(* Logix 5000 project; controller DNP3Master vendor 1 type 14 code 96 rev 19.13; software revision 19.01; part 5 of 5 *)

ADD_ON_INSTRUCTION PSDNP3EventG40V02   (* revision 1.0, vendor ProSoft Technology Inc *)
// Processes DNP3 Event and updates corresponding static DNP3 object. (Report by Exception.)
// G40V02 - Analog Output Status - 16bit with Status
VAR_IN_OUT
   EventBuffer : PSDNP3MasterEvent[1]; {required}
END_VAR
VAR_INPUT
   BufferSize : DINT; {required}
   CurrentBufferIndex : DINT; {required}
   Reset : BOOL; {required}
   OutstationNodeAddress : INT; {required}
   OutstationIPAddress0 : INT; {required}
   OutstationIPAddress1 : INT; {required}
   OutstationIPAddress2 : INT; {required}
   OutstationIPAddress3 : INT; {required}
END_VAR
VAR_IN_OUT
   DNP3StaticObject : PSDNP3AnalogOutputStatus16Flag[1]; {required}
END_VAR
VAR_INPUT
   MaxtElementCount : DINT; {required}
END_VAR
VAR_OUTPUT
   EventsProcessed : DINT; {access Read Only, visible}
   LastElementIndex : DINT; {access Read Only, visible}
   LastValue : DINT; {access Read Only, visible}
   LastStatus : SINT; {access Read Only, visible}
   CurrentUnloadIndex : DINT; {access Read Only, visible}
END_VAR
VAR
   UnloadIndex : DINT; {access None}
   EnableInTemp : BOOL; {access None}
   InitialScan : BOOL; {access None}
   EntryValidForProcessing : BOOL; {access None}
   ElementIndex : DINT; {access None}
   NextIndex : DINT; {access None}
   ResetPulse : BOOL; {access None}
   ResetONS : BOOL; {access None}
END_VAR

ROUTINE Logic   (* ladder *)
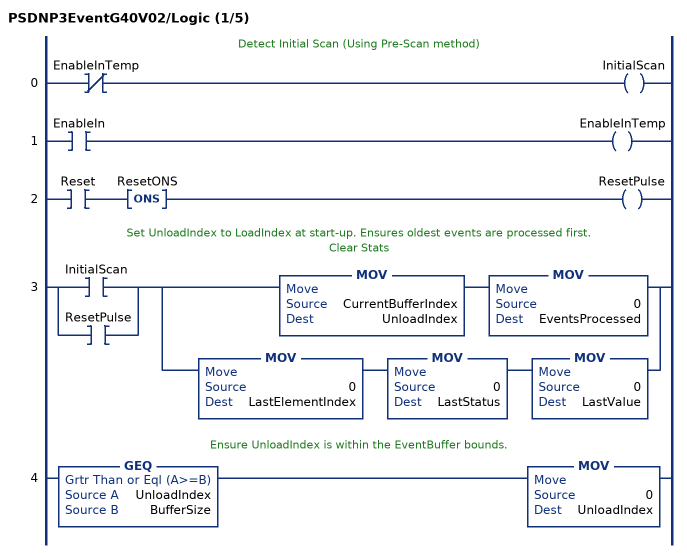
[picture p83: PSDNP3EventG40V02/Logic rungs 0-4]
   // Detect Initial Scan (Using Pre-Scan method)
   0: XIO(EnableInTemp)OTE(InitialScan);
   1: XIC(EnableIn)OTE(EnableInTemp);
   2: XIC(Reset)ONS(ResetONS)OTE(ResetPulse);
   // Set UnloadIndex to LoadIndex at start-up. Ensures oldest events are processed first.
   // Clear Stats
   3: [XIC(InitialScan) ,XIC(ResetPulse) ][MOV(CurrentBufferIndex,UnloadIndex) MOV(0,EventsProcessed) ,MOV(0,LastElementIndex) MOV(0,LastStatus) MOV(0,LastValue) ];
   // Ensure UnloadIndex is within the EventBuffer bounds.
   4: GEQ(UnloadIndex,BufferSize)MOV(0,UnloadIndex);
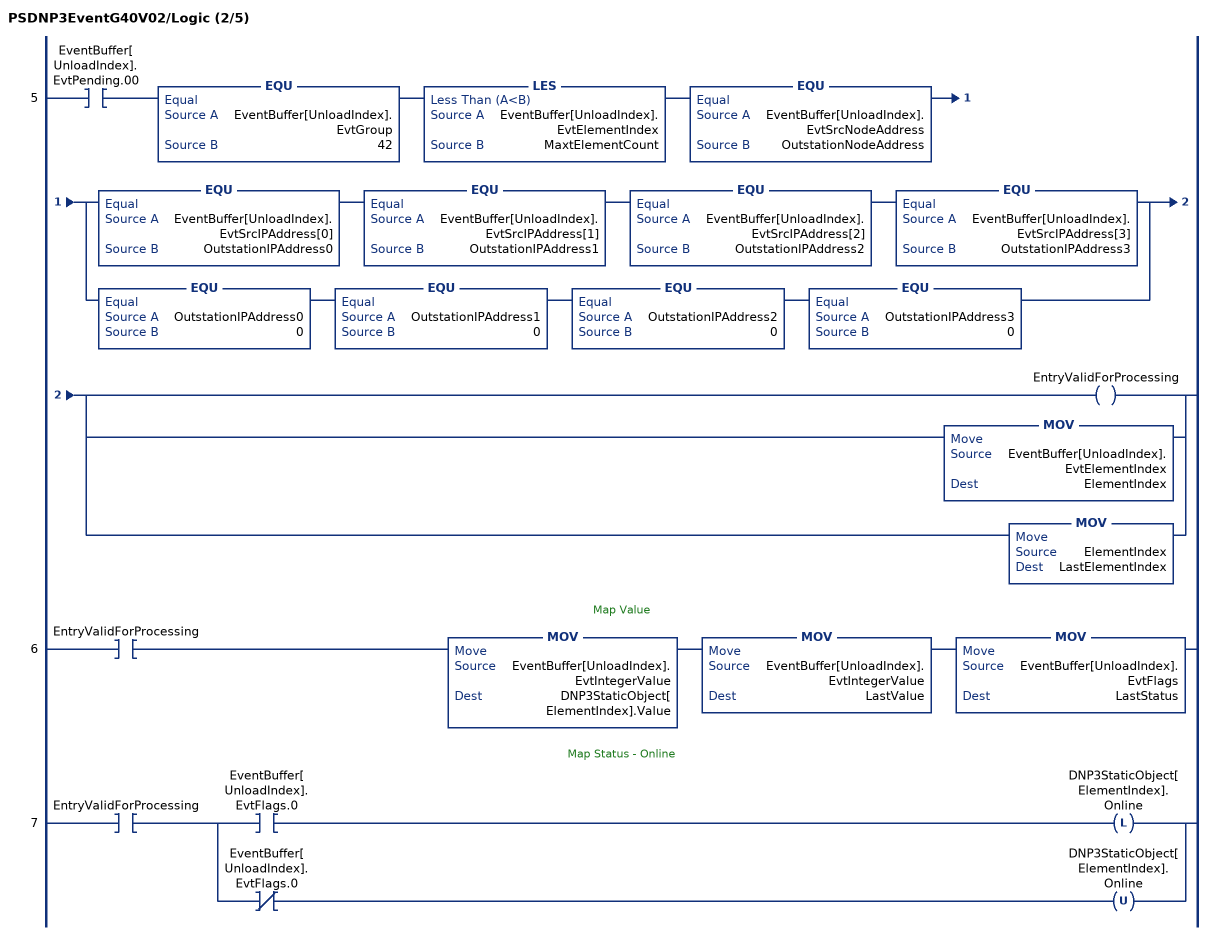
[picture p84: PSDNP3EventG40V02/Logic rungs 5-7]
   5: XIC(EventBuffer[UnloadIndex].EvtPending.00)EQU(EventBuffer[UnloadIndex].EvtGroup,42)LES(EventBuffer[UnloadIndex].EvtElementIndex,MaxtElementCount)EQU(EventBuffer[UnloadIndex].EvtSrcNodeAddress,OutstationNodeAddress)[EQU(EventBuffer[UnloadIndex].EvtSrcIPAddress[0],OutstationIPAddress0) EQU(EventBuffer[UnloadIndex].EvtSrcIPAddress[1],OutstationIPAddress1) EQU(EventBuffer[UnloadIndex].EvtSrcIPAddress[2],OutstationIPAddress2) EQU(EventBuffer[UnloadIndex].EvtSrcIPAddress[3],OutstationIPAddress3) ,EQU(OutstationIPAddress0,0) EQU(OutstationIPAddress1,0) EQU(OutstationIPAddress2,0) EQU(OutstationIPAddress3,0) ][OTE(EntryValidForProcessing) ,MOV(EventBuffer[UnloadIndex].EvtElementIndex,ElementIndex) ,MOV(ElementIndex,LastElementIndex) ];
   // Map Value
   6: XIC(EntryValidForProcessing)MOV(EventBuffer[UnloadIndex].EvtIntegerValue,DNP3StaticObject[ElementIndex].Value)MOV(EventBuffer[UnloadIndex].EvtIntegerValue,LastValue)MOV(EventBuffer[UnloadIndex].EvtFlags,LastStatus);
   // Map Status - Online
   7: XIC(EntryValidForProcessing)[XIC(EventBuffer[UnloadIndex].EvtFlags.0) OTL(DNP3StaticObject[ElementIndex].Online) ,XIO(EventBuffer[UnloadIndex].EvtFlags.0) OTU(DNP3StaticObject[ElementIndex].Online) ];
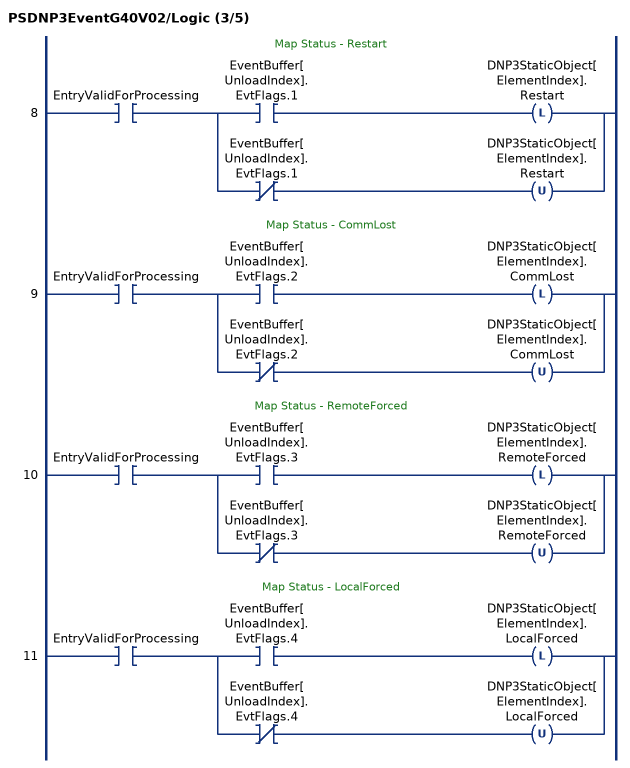
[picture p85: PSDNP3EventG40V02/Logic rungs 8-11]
   // Map Status - Restart
   8: XIC(EntryValidForProcessing)[XIC(EventBuffer[UnloadIndex].EvtFlags.1) OTL(DNP3StaticObject[ElementIndex].Restart) ,XIO(EventBuffer[UnloadIndex].EvtFlags.1) OTU(DNP3StaticObject[ElementIndex].Restart) ];
   // Map Status - CommLost
   9: XIC(EntryValidForProcessing)[XIC(EventBuffer[UnloadIndex].EvtFlags.2) OTL(DNP3StaticObject[ElementIndex].CommLost) ,XIO(EventBuffer[UnloadIndex].EvtFlags.2) OTU(DNP3StaticObject[ElementIndex].CommLost) ];
   // Map Status - RemoteForced
   10: XIC(EntryValidForProcessing)[XIC(EventBuffer[UnloadIndex].EvtFlags.3) OTL(DNP3StaticObject[ElementIndex].RemoteForced) ,XIO(EventBuffer[UnloadIndex].EvtFlags.3) OTU(DNP3StaticObject[ElementIndex].RemoteForced) ];
   // Map Status - LocalForced
   11: XIC(EntryValidForProcessing)[XIC(EventBuffer[UnloadIndex].EvtFlags.4) OTL(DNP3StaticObject[ElementIndex].LocalForced) ,XIO(EventBuffer[UnloadIndex].EvtFlags.4) OTU(DNP3StaticObject[ElementIndex].LocalForced) ];
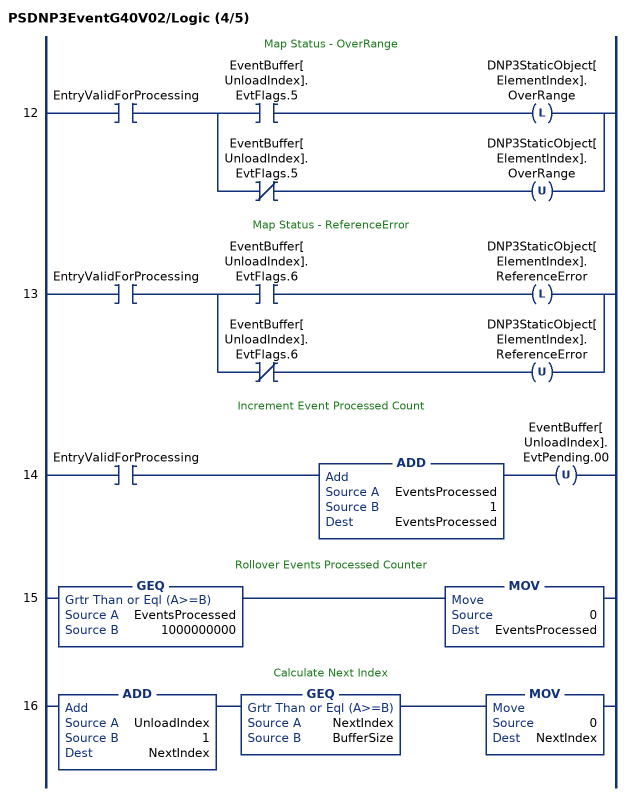
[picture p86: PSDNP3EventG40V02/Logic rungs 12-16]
   // Map Status - OverRange
   12: XIC(EntryValidForProcessing)[XIC(EventBuffer[UnloadIndex].EvtFlags.5) OTL(DNP3StaticObject[ElementIndex].OverRange) ,XIO(EventBuffer[UnloadIndex].EvtFlags.5) OTU(DNP3StaticObject[ElementIndex].OverRange) ];
   // Map Status - ReferenceError
   13: XIC(EntryValidForProcessing)[XIC(EventBuffer[UnloadIndex].EvtFlags.6) OTL(DNP3StaticObject[ElementIndex].ReferenceError) ,XIO(EventBuffer[UnloadIndex].EvtFlags.6) OTU(DNP3StaticObject[ElementIndex].ReferenceError) ];
   // Increment Event Processed Count
   14: XIC(EntryValidForProcessing)ADD(EventsProcessed,1,EventsProcessed)OTU(EventBuffer[UnloadIndex].EvtPending.00);
   // Rollover Events Processed Counter
   15: GEQ(EventsProcessed,1000000000)MOV(0,EventsProcessed);
   // Calculate Next Index
   16: ADD(UnloadIndex,1,NextIndex)GEQ(NextIndex,BufferSize)MOV(0,NextIndex);
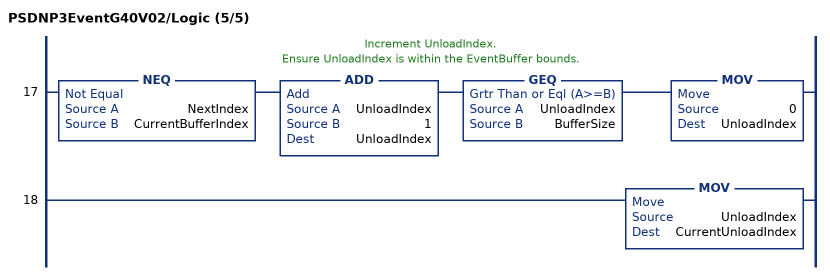
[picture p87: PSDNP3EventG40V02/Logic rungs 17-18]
   // Increment UnloadIndex.
   // Ensure UnloadIndex is within the EventBuffer bounds.
   17: NEQ(NextIndex,CurrentBufferIndex)ADD(UnloadIndex,1,UnloadIndex)GEQ(UnloadIndex,BufferSize)MOV(0,UnloadIndex);
   18: MOV(UnloadIndex,CurrentUnloadIndex);
END_ROUTINE
END_ADD_ON_INSTRUCTION

ADD_ON_INSTRUCTION PSDNP3EventG40V03   (* revision 1.0, vendor ProSoft Technology Inc *)
// Processes DNP3 Event and updates corresponding static DNP3 object. (Report by Exception.)
// G40V03 - Analog Output Status - Real with Status
VAR_IN_OUT
   EventBuffer : PSDNP3MasterEvent[1]; {required}
END_VAR
VAR_INPUT
   BufferSize : DINT; {required}
   CurrentBufferIndex : DINT; {required}
   Reset : BOOL; {required}
   OutstationNodeAddress : INT; {required}
   OutstationIPAddress0 : INT; {required}
   OutstationIPAddress1 : INT; {required}
   OutstationIPAddress2 : INT; {required}
   OutstationIPAddress3 : INT; {required}
END_VAR
VAR_IN_OUT
   DNP3StaticObject : PSDNP3AnalogOutputStatusRealFlag[1]; {required}
END_VAR
VAR_INPUT
   MaxtElementCount : DINT; {required}
END_VAR
VAR_OUTPUT
   EventsProcessed : DINT; {access Read Only, visible}
   LastElementIndex : DINT; {access Read Only, visible}
   LastValue : REAL; {access Read Only, visible}
   LastStatus : SINT; {access Read Only, visible}
   CurrentUnloadIndex : DINT; {access Read Only, visible}
END_VAR
VAR
   UnloadIndex : DINT; {access None}
   EnableInTemp : BOOL; {access None}
   InitialScan : BOOL; {access None}
   EntryValidForProcessing : BOOL; {access None}
   ElementIndex : DINT; {access None}
   NextIndex : DINT; {access None}
   ResetPulse : BOOL; {access None}
   ResetONS : BOOL; {access None}
END_VAR

ROUTINE Logic   (* ladder *)
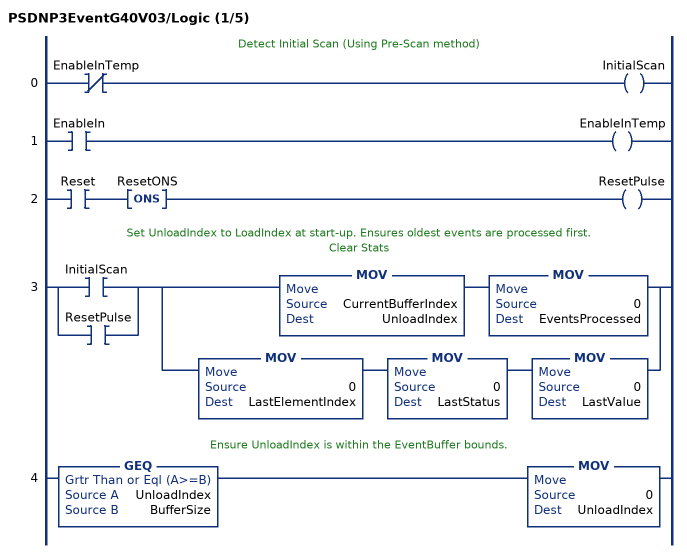
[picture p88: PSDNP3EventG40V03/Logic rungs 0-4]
   // Detect Initial Scan (Using Pre-Scan method)
   0: XIO(EnableInTemp)OTE(InitialScan);
   1: XIC(EnableIn)OTE(EnableInTemp);
   2: XIC(Reset)ONS(ResetONS)OTE(ResetPulse);
   // Set UnloadIndex to LoadIndex at start-up. Ensures oldest events are processed first.
   // Clear Stats
   3: [XIC(InitialScan) ,XIC(ResetPulse) ][MOV(CurrentBufferIndex,UnloadIndex) MOV(0,EventsProcessed) ,MOV(0,LastElementIndex) MOV(0,LastStatus) MOV(0,LastValue) ];
   // Ensure UnloadIndex is within the EventBuffer bounds.
   4: GEQ(UnloadIndex,BufferSize)MOV(0,UnloadIndex);
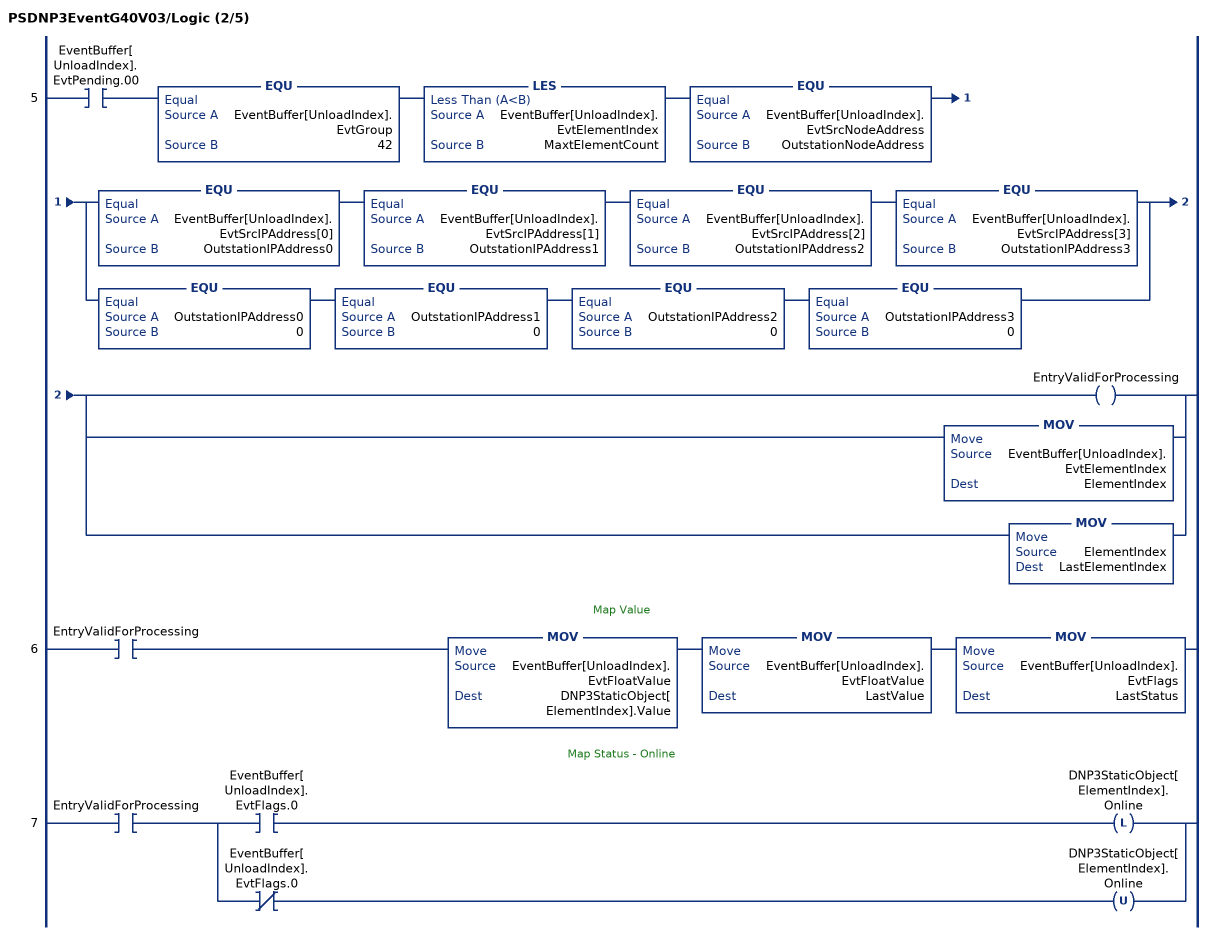
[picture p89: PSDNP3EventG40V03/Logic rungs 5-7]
   5: XIC(EventBuffer[UnloadIndex].EvtPending.00)EQU(EventBuffer[UnloadIndex].EvtGroup,42)LES(EventBuffer[UnloadIndex].EvtElementIndex,MaxtElementCount)EQU(EventBuffer[UnloadIndex].EvtSrcNodeAddress,OutstationNodeAddress)[EQU(EventBuffer[UnloadIndex].EvtSrcIPAddress[0],OutstationIPAddress0) EQU(EventBuffer[UnloadIndex].EvtSrcIPAddress[1],OutstationIPAddress1) EQU(EventBuffer[UnloadIndex].EvtSrcIPAddress[2],OutstationIPAddress2) EQU(EventBuffer[UnloadIndex].EvtSrcIPAddress[3],OutstationIPAddress3) ,EQU(OutstationIPAddress0,0) EQU(OutstationIPAddress1,0) EQU(OutstationIPAddress2,0) EQU(OutstationIPAddress3,0) ][OTE(EntryValidForProcessing) ,MOV(EventBuffer[UnloadIndex].EvtElementIndex,ElementIndex) ,MOV(ElementIndex,LastElementIndex) ];
   // Map Value
   6: XIC(EntryValidForProcessing)MOV(EventBuffer[UnloadIndex].EvtFloatValue,DNP3StaticObject[ElementIndex].Value)MOV(EventBuffer[UnloadIndex].EvtFloatValue,LastValue)MOV(EventBuffer[UnloadIndex].EvtFlags,LastStatus);
   // Map Status - Online
   7: XIC(EntryValidForProcessing)[XIC(EventBuffer[UnloadIndex].EvtFlags.0) OTL(DNP3StaticObject[ElementIndex].Online) ,XIO(EventBuffer[UnloadIndex].EvtFlags.0) OTU(DNP3StaticObject[ElementIndex].Online) ];
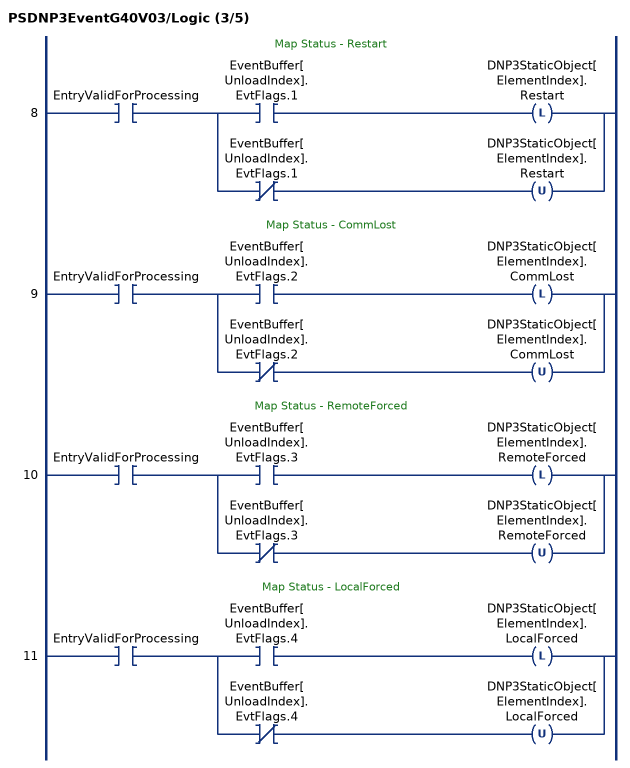
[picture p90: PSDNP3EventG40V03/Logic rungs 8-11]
   // Map Status - Restart
   8: XIC(EntryValidForProcessing)[XIC(EventBuffer[UnloadIndex].EvtFlags.1) OTL(DNP3StaticObject[ElementIndex].Restart) ,XIO(EventBuffer[UnloadIndex].EvtFlags.1) OTU(DNP3StaticObject[ElementIndex].Restart) ];
   // Map Status - CommLost
   9: XIC(EntryValidForProcessing)[XIC(EventBuffer[UnloadIndex].EvtFlags.2) OTL(DNP3StaticObject[ElementIndex].CommLost) ,XIO(EventBuffer[UnloadIndex].EvtFlags.2) OTU(DNP3StaticObject[ElementIndex].CommLost) ];
   // Map Status - RemoteForced
   10: XIC(EntryValidForProcessing)[XIC(EventBuffer[UnloadIndex].EvtFlags.3) OTL(DNP3StaticObject[ElementIndex].RemoteForced) ,XIO(EventBuffer[UnloadIndex].EvtFlags.3) OTU(DNP3StaticObject[ElementIndex].RemoteForced) ];
   // Map Status - LocalForced
   11: XIC(EntryValidForProcessing)[XIC(EventBuffer[UnloadIndex].EvtFlags.4) OTL(DNP3StaticObject[ElementIndex].LocalForced) ,XIO(EventBuffer[UnloadIndex].EvtFlags.4) OTU(DNP3StaticObject[ElementIndex].LocalForced) ];
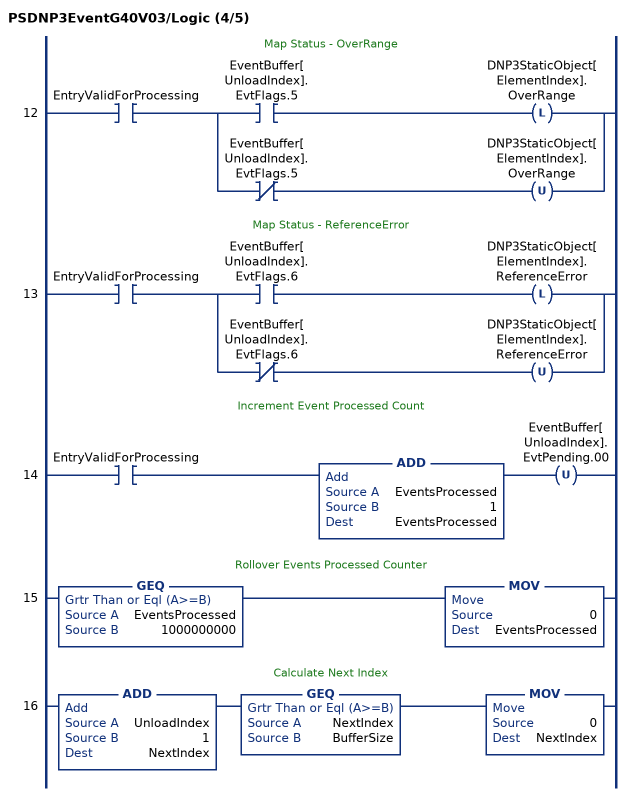
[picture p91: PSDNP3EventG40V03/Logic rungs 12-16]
   // Map Status - OverRange
   12: XIC(EntryValidForProcessing)[XIC(EventBuffer[UnloadIndex].EvtFlags.5) OTL(DNP3StaticObject[ElementIndex].OverRange) ,XIO(EventBuffer[UnloadIndex].EvtFlags.5) OTU(DNP3StaticObject[ElementIndex].OverRange) ];
   // Map Status - ReferenceError
   13: XIC(EntryValidForProcessing)[XIC(EventBuffer[UnloadIndex].EvtFlags.6) OTL(DNP3StaticObject[ElementIndex].ReferenceError) ,XIO(EventBuffer[UnloadIndex].EvtFlags.6) OTU(DNP3StaticObject[ElementIndex].ReferenceError) ];
   // Increment Event Processed Count
   14: XIC(EntryValidForProcessing)ADD(EventsProcessed,1,EventsProcessed)OTU(EventBuffer[UnloadIndex].EvtPending.00);
   // Rollover Events Processed Counter
   15: GEQ(EventsProcessed,1000000000)MOV(0,EventsProcessed);
   // Calculate Next Index
   16: ADD(UnloadIndex,1,NextIndex)GEQ(NextIndex,BufferSize)MOV(0,NextIndex);
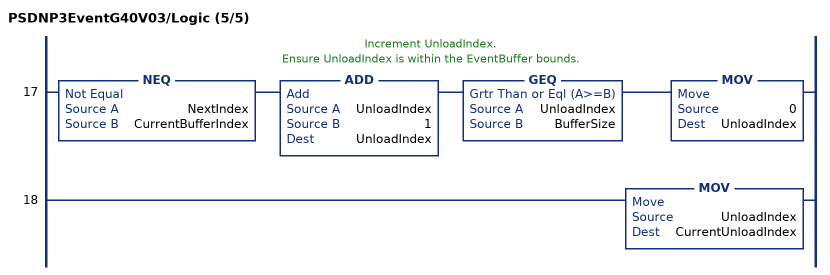
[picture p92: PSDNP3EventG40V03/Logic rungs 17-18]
   // Increment UnloadIndex.
   // Ensure UnloadIndex is within the EventBuffer bounds.
   17: NEQ(NextIndex,CurrentBufferIndex)ADD(UnloadIndex,1,UnloadIndex)GEQ(UnloadIndex,BufferSize)MOV(0,UnloadIndex);
   18: MOV(UnloadIndex,CurrentUnloadIndex);
END_ROUTINE
END_ADD_ON_INSTRUCTION

VAR_GLOBAL   (* controller tags *)
   DNP3G01V01 : PSDNP3BinaryInputPacked[10] := ([0].BinaryValues[0] := 9, [0].BinaryValues[1] := 1, [0].BinaryValues[2] := 1, [0].BinaryValues[3] := -64);
   DNP3G01V02 : PSDNP3BinaryInputWithFlag[100];
   DNP3G01V02_RBE : PSDNP3EventG01V02 := (BufferSize := 100, CurrentBufferIndex := 10, Reset := 1, OutstationNodeAddress := 2, MaxtElementCount := 10, EventsProcessed := 3, LastStatus := 81, CurrentUnloadIndex := 9);
   DNP3G03V01 : PSDNP3DoubleBinaryInputPacked[10];
   DNP3G03V02 : PSDNP3DoubleBinaryInputWithFlag[10] := ([0].Online := 1, [0].LocalForced := 1, [0].State0 := 1, [0].State1 := 1, [1].State1 := 1, [9].Online := 1, [9].CommLost := 1, [9].LocalForced := 1, [9].State0 := 1);
   DNP3G03V02_RBE : PSDNP3EventG03V02 := (BufferSize := 100, CurrentBufferIndex := 10, Reset := 1, OutstationNodeAddress := 2, MaxtElementCount := 10, EventsProcessed := 6, LastElementIndex := 1, LastValue := 2, CurrentUnloadIndex := 9);
   DNP3G10V0 : PSDNP3BinaryOutputWithFlag[10] := ([0].Online := 1, [0].CommLost := 1, [0].LocalForced := 1, [0].Reserved2 := 1, [2].Online := 1, [2].State := 1);
   DNP3G10V01 : PSDNP3BinaryOutputPacked[10];
   DNP3G10V02 : PSDNP3BinaryOutputWithFlag[10] := ([0].Online := 1, [0].LocalForced := 1, [0].Reserved2 := 1, [0].State := 1, [1].Online := 1, [1].Restart := 1, [9].Online := 1, [9].CommLost := 1, [9].LocalForced := 1);
   DNP3G10V02_RBE : PSDNP3EventG10V02 := (BufferSize := 100, CurrentBufferIndex := 10, Reset := 1, OutstationNodeAddress := 2, MaxtElementCount := 10, EventsProcessed := 5, LastValue := 1, LastStatus := 81, CurrentUnloadIndex := 9);
   DNP3G110V01 : STRING[5];
   DNP3G12V01 : PSDNP3CROB[10] := ([0].ControlCode := 4, [0].Count := 5, [0].OnTime := 200, [0].OffTime := 380, [3].RequestPending := 1, [3].ControlCode := 3, [3].Count := 1, [3].OnTime := 100, [3].OffTime := 100);
   DNP3G1V0 : PSDNP3BinaryInputWithFlag[10] := ([0].Online := 1, [0].LocalForced := 1, [0].State := 1, [1].Online := 1, [2].Online := 1, [2].Restart := 1, [2].CommLost := 1, [4].Online := 1, [4].Restart := 1, [4].CommLost := 1, [4].RemoteForced := 1, [4].LocalForced := 1, [5].State := 1, [7].State := 1, [8].State := 1, [9].State := 1);
   DNP3G20_Freeze : PSDNP3FreezeCmd[10];
   DNP3G20V0 : PSDNP3Counter32WithFlag[10];
   DNP3G20V01 : PSDNP3Counter32WithFlag[10];
   DNP3G20V01_RBE : PSDNP3EventG20V01 := (BufferSize := 100, CurrentBufferIndex := 10, Reset := 1, OutstationNodeAddress := 2, MaxtElementCount := 10, EventsProcessed := 2, LastValue := 17, LastStatus := 19, CurrentUnloadIndex := 9);
   DNP3G20V02 : PSDNP3Counter16WithFlag[10];
   DNP3G20V05 : DINT[10] := ([0] := 143, [1] := 144, [2] := 145, [3] := 146, [4] := 147, [5] := 148, [6] := 149, [7] := 150, [8] := 151, [9] := 3456);
   DNP3G20V06 : INT[10] := ([0] := 6, [1] := 154, [2] := 155, [3] := 156, [4] := 157, [5] := 158, [6] := 159, [7] := 160, [8] := 161, [9] := 3456);
   DNP3G21V0 : PSDNP3FrozenCounter32WithFlagTime[10];
   DNP3G21V01 : PSDNP3FrozenCounter32WithFlag[10] := ([0].LocalForced := 1, [0].Value := 88, [1].Online := 1, [1].Value := 324, [2].Restart := 1, [2].CommLost := 1, [2].Value := 100268, [9].Online := 1, [9].CommLost := 1, [9].LocalForced := 1, [9].Discontinuity := 1, [9].Value := 3456);
   DNP3G21V01_RBE : PSDNP3EventG21V01 := (BufferSize := 100, CurrentBufferIndex := 10, Reset := 1, OutstationNodeAddress := 2, MaxtElementCount := 10, EventsProcessed := 10, LastValue := 88, LastStatus := 16, CurrentUnloadIndex := 9);
   DNP3G21V02 : PSDNP3FrozenCounter16WithFlag[10] := ([0].Online := 1, [0].Value := 32000, [5].Restart := 1, [5].CommLost := 1, [5].Value := 31000, [9].Online := 1, [9].CommLost := 1, [9].LocalForced := 1, [9].Discontinuity := 1, [9].Value := 3456);
   DNP3G21V05 : PSDNP3FrozenCounter32WithFlagTime[100];
   DNP3G21V05_RBE : PSDNP3EventG21V05 := (BufferSize := 100, CurrentBufferIndex := 13, Reset := 1, OutstationNodeAddress := 2, MaxtElementCount := 10, EventsProcessed := 73, LastValue := 77, LastStatus := 16, CurrentUnloadIndex := 12);
   DNP3G21V06 : PSDNP3FrozenCounter16WithFlagTime[10] := ([0].Online := 1, [0].Value := 3, [9].Online := 1, [9].CommLost := 1, [9].LocalForced := 1, [9].Discontinuity := 1, [9].Value := 3456, [9].TimeOfOccurrence := 1484716130000200);
   DNP3G21V09 : DINT[10] := ([9] := 3456);
   DNP3G21V10 : INT[10] := ([0] := 6, [9] := 3456);
   DNP3G30_Freeze : PSDNP3FreezeCmd[10];
   DNP3G30V0 : PSDNP3AnalogInputVar0[10];
   DNP3G30V01 : PSDNP3AnalogInput32Flag[10];
   DNP3G30V02 : PSDNP3AnalogInput16Flag[10] := ([9].Online := 1, [9].Restart := 1, [9].CommLost := 1, [9].Value := 3456);
   DNP3G30V03 : DINT[10] := ([9] := 3456);
   DNP3G30V04 : INT[10] := ([9] := 3456);
   DNP3G30V05 : PSDNP3AnalogInputRealFlag[100];
   DNP3G30V05_RBE : PSDNP3EventG30V05 := (BufferSize := 100, CurrentBufferIndex := 10, Reset := 1, OutstationNodeAddress := 2, MaxtElementCount := 10, EventsProcessed := 2, LastValue := 345.0, LastStatus := 1, CurrentUnloadIndex := 9);
   DNP3G31V01 : PSDNP3FrozenAnalog32WithFlag[10];
   DNP3G31V02 : PSDNP3FrozenAnalog16WithFlag[10];
   DNP3G31V03 : PSDNP3FrozenAnalog32WithFlagTime[10];
   DNP3G31V04 : PSDNP3FrozenAnalog16WithFlagTime[10];
   DNP3G31V05 : DINT[10];
   DNP3G31V06 : INT[10];
   DNP3G31V07 : PSDNP3FrozenAnalogRealWithFlag[10];
   DNP3G3V0 : PSDNP3DoubleBinaryInputWithFlag[10];
   DNP3G40V0 : PSDNP3AnalogOutputVar0[10];
   DNP3G40V01 : PSDNP3AnalogOutputStatus32Flag[10] := ([0].Online := 1, [0].Value := 56, [9].Online := 1, [9].CommLost := 1, [9].LocalForced := 1, [9].ReferenceError := 1, [9].Value := 3456);
   DNP3G40V02 : PSDNP3AnalogOutputStatus16Flag[10] := ([0].Online := 1, [0].Value := 123, [9].Online := 1, [9].CommLost := 1, [9].LocalForced := 1, [9].ReferenceError := 1, [9].Value := 3456);
   DNP3G40V03 : PSDNP3AnalogOutputStatusRealFlag[10] := ([0].Online := 1, [0].Value := 66.0, [1].Online := 1, [1].Value := 760.0, [9].Online := 1, [9].CommLost := 1, [9].LocalForced := 1, [9].ReferenceError := 1, [9].Value := 71.25);
   DNP3G40V03_RBE : PSDNP3EventG40V03 := (BufferSize := 100, CurrentBufferIndex := 10, Reset := 1, OutstationNodeAddress := 2, MaxtElementCount := 10, EventsProcessed := 2, LastValue := 66.0, LastStatus := 1, CurrentUnloadIndex := 9);
   DNP3G41V01 : PSDNP3AnalogOutput32[10] := ([0].Value := 56, [7].RequestPending := 1, [7].Value := 77);
   DNP3G41V02 : PSDNP3AnalogOutput16[10] := ([0].Value := 123);
   DNP3G41V03 : PSDNP3AnalogOutputReal[10] := ([0].Value := 33.56);
   DNP3MasterEventBuffer : PSDNP3MasterEvent[100];
   DNP3MasterUnloadReset : BOOL := 1;
   DNP3Message : MESSAGE;
        MessageParameters(ServiceCode := 16#006a, LocalElement := DNP3MsgRequest, DestinationTag := DNP3MsgResponse, ...)
   DNP3MsgRequest : PSDNP3MsgRequest := (DestinationNode := 1, RequestDataSize := 5, IPAddress[0] := 192, IPAddress[1] := 168, IPAddress[2] := 1, IPAddress[3] := 210, Function := 1);
   DNP3MsgResponse : PSDNP3MsgResponse;
   DNPMessageTrigger : BOOL;
   PLX51DNPMInput : PLX51DNPInput;
   PLX51DNPMOutput : PLX51DNPOutput;
END_VAR

PROGRAM DNP3Events   (* main routine Main *)

ROUTINE FromOutstation_01   (* ladder *)
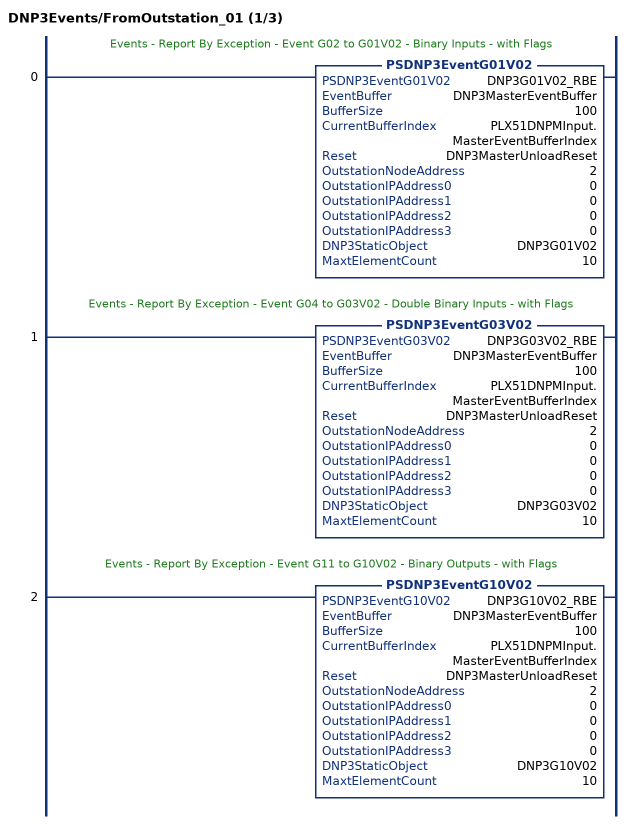
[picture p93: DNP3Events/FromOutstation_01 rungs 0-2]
   // Events - Report By Exception - Event G02 to G01V02 - Binary Inputs - with Flags
   0: PSDNP3EventG01V02(DNP3G01V02_RBE,DNP3MasterEventBuffer,100,PLX51DNPMInput.MasterEventBufferIndex,DNP3MasterUnloadReset,2,0,0,0,0,DNP3G01V02,10);
   // Events - Report By Exception - Event G04 to G03V02 - Double Binary Inputs - with Flags
   1: PSDNP3EventG03V02(DNP3G03V02_RBE,DNP3MasterEventBuffer,100,PLX51DNPMInput.MasterEventBufferIndex,DNP3MasterUnloadReset,2,0,0,0,0,DNP3G03V02,10);
   // Events - Report By Exception - Event G11 to G10V02 - Binary Outputs - with Flags
   2: PSDNP3EventG10V02(DNP3G10V02_RBE,DNP3MasterEventBuffer,100,PLX51DNPMInput.MasterEventBufferIndex,DNP3MasterUnloadReset,2,0,0,0,0,DNP3G10V02,10);
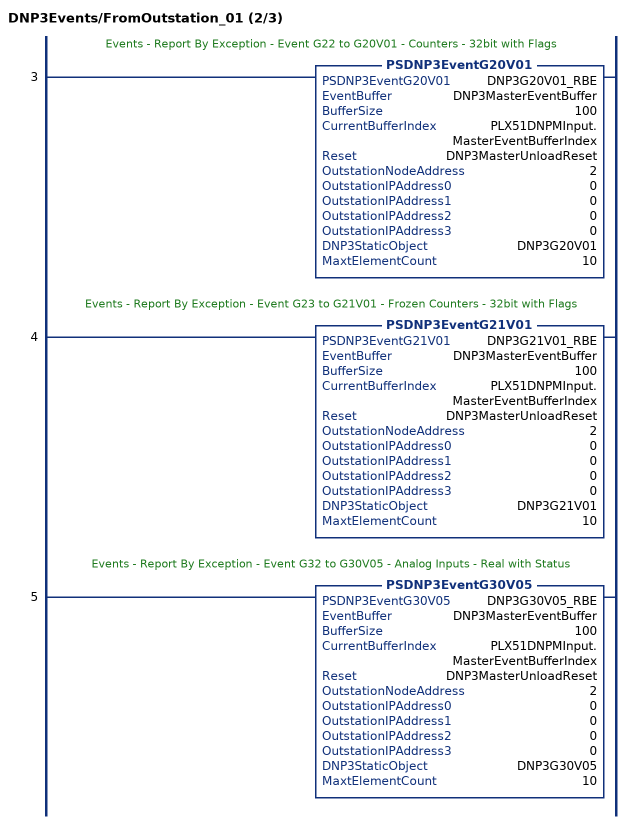
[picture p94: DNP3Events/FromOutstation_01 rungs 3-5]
   // Events - Report By Exception - Event G22 to G20V01 - Counters - 32bit with Flags
   3: PSDNP3EventG20V01(DNP3G20V01_RBE,DNP3MasterEventBuffer,100,PLX51DNPMInput.MasterEventBufferIndex,DNP3MasterUnloadReset,2,0,0,0,0,DNP3G20V01,10);
   // Events - Report By Exception - Event G23 to G21V01 - Frozen Counters - 32bit with Flags
   4: PSDNP3EventG21V01(DNP3G21V01_RBE,DNP3MasterEventBuffer,100,PLX51DNPMInput.MasterEventBufferIndex,DNP3MasterUnloadReset,2,0,0,0,0,DNP3G21V01,10);
   // Events - Report By Exception - Event G32 to G30V05 - Analog Inputs - Real with Status
   5: PSDNP3EventG30V05(DNP3G30V05_RBE,DNP3MasterEventBuffer,100,PLX51DNPMInput.MasterEventBufferIndex,DNP3MasterUnloadReset,2,0,0,0,0,DNP3G30V05,10);
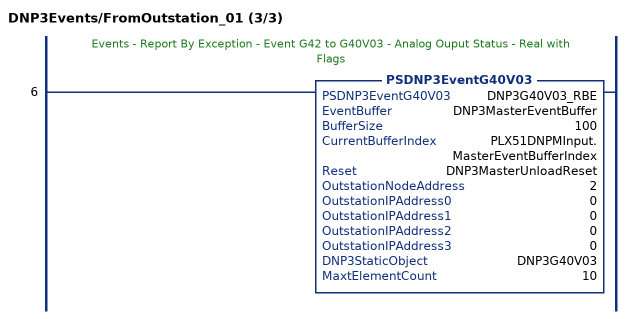
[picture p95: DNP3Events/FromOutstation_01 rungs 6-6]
   // Events - Report By Exception - Event G42 to G40V03 - Analog Ouput Status - Real with Flags
   6: PSDNP3EventG40V03(DNP3G40V03_RBE,DNP3MasterEventBuffer,100,PLX51DNPMInput.MasterEventBufferIndex,DNP3MasterUnloadReset,2,0,0,0,0,DNP3G40V03,10);
END_ROUTINE

ROUTINE Main   (* ladder *)
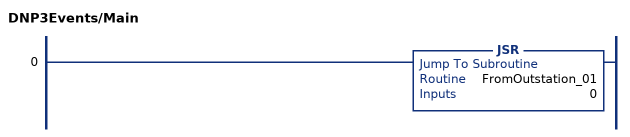
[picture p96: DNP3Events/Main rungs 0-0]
   0: JSR(FromOutstation_01,0);
END_ROUTINE
END_PROGRAM

PROGRAM MainProgram   (* main routine MainRoutine *)

ROUTINE DNP3Router   (* ladder *)
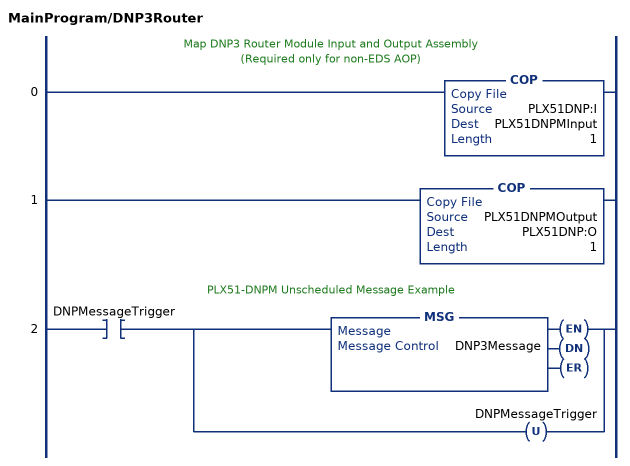
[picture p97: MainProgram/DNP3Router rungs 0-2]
   // Map DNP3 Router Module Input and Output Assembly
   //  (Required only for non-EDS AOP)
   0: COP(PLX51DNP:I,PLX51DNPMInput,1);
   1: COP(PLX51DNPMOutput,PLX51DNP:O,1);
   // PLX51-DNPM Unscheduled Message Example
   2: XIC(DNPMessageTrigger)[MSG(DNP3Message) ,OTU(DNPMessageTrigger) ];
END_ROUTINE

ROUTINE MainRoutine   (* ladder *)
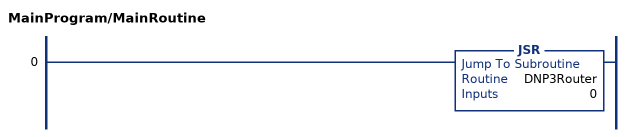
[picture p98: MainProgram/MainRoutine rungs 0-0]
   0: JSR(DNP3Router,0);
END_ROUTINE
END_PROGRAM
